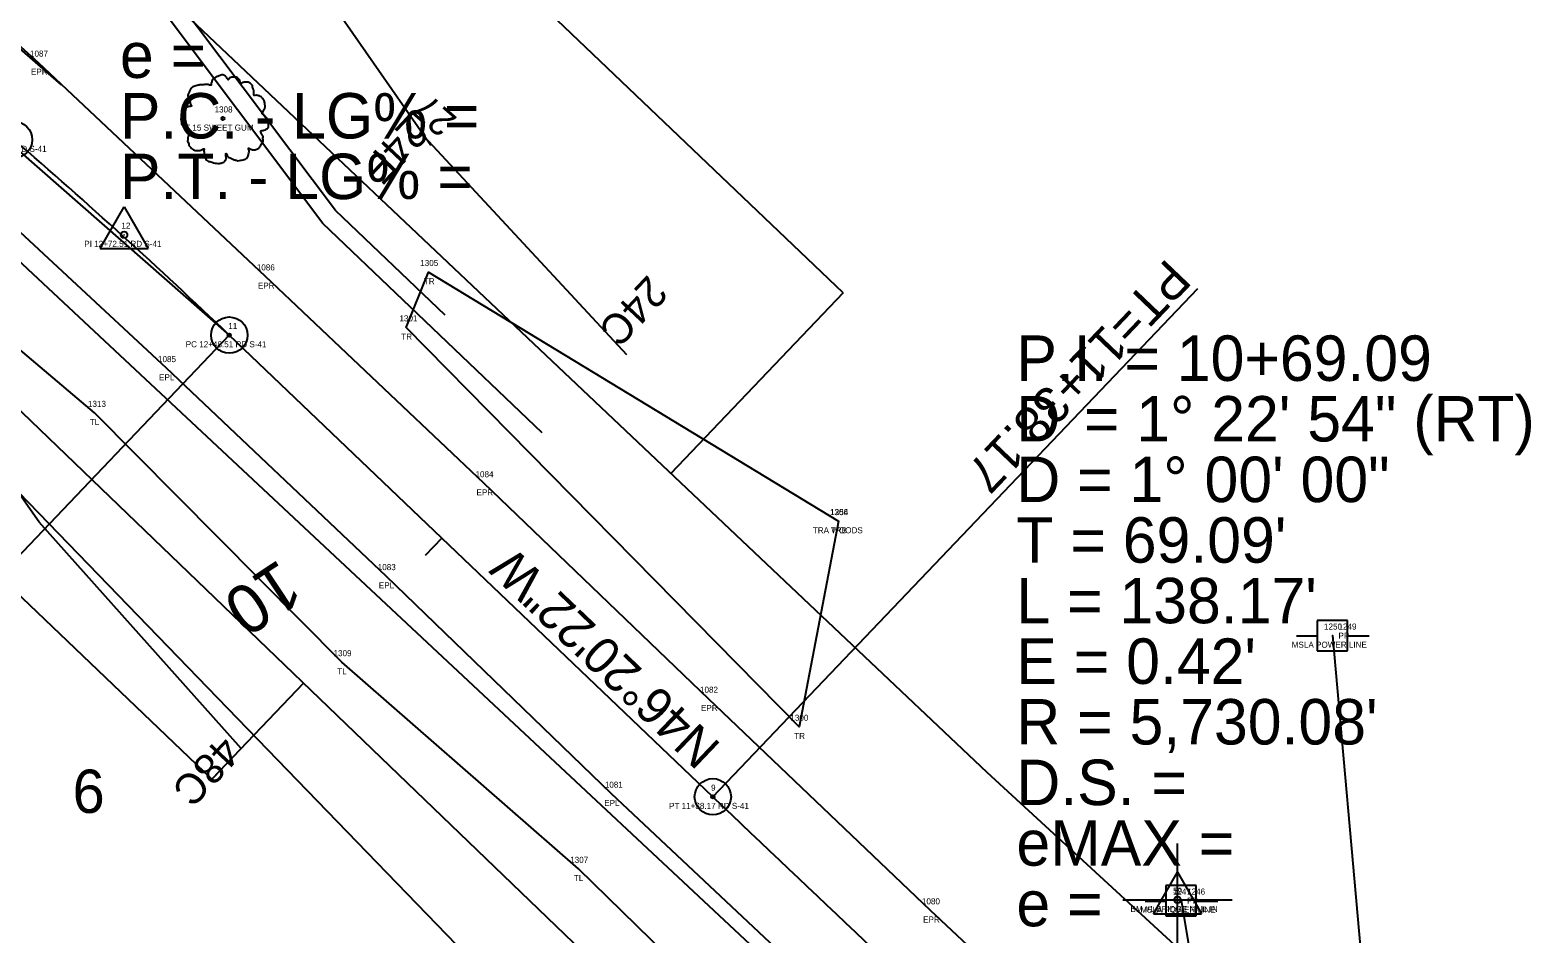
# Model space of a CAD drawing. Extents: x 1812113 to 1819860, y 1177395 to 1181185.
# Drawn here: x 1813853.2 to 1814102.1, y 1178492.8 to 1178641.9 of the extents above; entities that cross this region are included whole.
import ezdxf

# ---------------------------------------------------------------- set-up
doc = ezdxf.new("R2010")
doc.units = 0
for name, color, linetype in [('RD_EX_DV_Prop', 7, 'Continuous'), ('RD_EX_DV_TX_Prop', 7, 'Continuous'), ('RD_EX_Misc', 7, 'Continuous'), ('RD_EX_Misc_txCode', 7, 'Continuous'), ('RD_EX_Road', 7, 'Continuous'), ('RD_EX_Road_txCode', 7, 'Continuous'), ('RD_EX_UT', 7, 'Continuous'), ('RD_EX_UT_txCode', 7, 'Continuous'), ('RD_EX_VEG', 7, 'Continuous'), ('RD_EX_VEG_txCode', 7, 'Continuous'), ('RD_HC_CL', 7, 'Continuous'), ('RD_HC_Data', 7, 'Continuous'), ('RD_HC_Data_Tic', 7, 'Continuous'), ('RD_HC_TX_StaOther', 7, 'Continuous'), ('RD_HC_txCode', 7, 'Continuous'), ('RD_PD_ALT1_TrvlWay', 7, 'Continuous'), ('RD_PD_ALT3_LnLine', 7, 'Continuous'), ('RD_PD_BCA', 7, 'Continuous'), ('RD_PD_PatLn1', 7, 'Continuous'), ('RD_PD_PatLn2', 7, 'Continuous'), ('RD_PD_RW', 7, 'Continuous'), ('RD_SMD_Locator', 7, 'Continuous')]:
    doc.layers.add(name, color=color, linetype=linetype)

msp = doc.modelspace()

# ---------------------------------------------------------------- linework, layer by layer
at = {"layer": 'RD_EX_DV_Prop'}
for p, q in [((1814011.17, 1178519.35), (1813854.67, 1178667.32)), ((1814007.16, 1178429.49), (1813828.61, 1178601.13)), ((1814146.51, 1178395.03), (1814011.17, 1178519.35))]:
    msp.add_line(p, q, dxfattribs=at)
at = {"layer": 'RD_EX_Misc'}
for p, q in [((1814068.17, 1178541.96), (1814086.12, 1178341.27)), ((1814043.18, 1178498.23), (1814070.2, 1178336.93))]:
    msp.add_line(p, q, dxfattribs=at)
at = {"layer": 'RD_EX_Road'}
for p, q in [((1813875.67, 1178586.1), (1813838.32, 1178620.7)), ((1813911.94, 1178551.77), (1813875.67, 1178586.1)), ((1813949.15, 1178515.86), (1813911.94, 1178551.77)), ((1813986.47, 1178480.85), (1813949.15, 1178515.86))]:
    msp.add_line(p, q, dxfattribs=at)
msp.add_lwpolyline([(1814076.45, 1178427.4), (1814038.86, 1178461.87), (1814001.83, 1178496.62), (1813965.15, 1178531.54), (1813928.08, 1178567.1), (1813892.01, 1178601.23), (1813854.54, 1178636.51), (1813817.44, 1178670.03), (1813779.87, 1178701.64)], dxfattribs=at)
at = {"layer": 'RD_EX_UT'}
for p, q in [((1814070.66, 1178544.47), (1814065.66, 1178544.47)), ((1814065.66, 1178544.47), (1814065.66, 1178539.47)), ((1814070.66, 1178539.47), (1814070.66, 1178544.47)), ((1814062.23, 1178541.91), (1814065.7, 1178541.91)), ((1814070.59, 1178541.91), (1814074.23, 1178541.91)), ((1814065.66, 1178539.47), (1814070.66, 1178539.47)), ((1814045.67, 1178500.74), (1814040.67, 1178500.74)), ((1814040.67, 1178500.74), (1814040.67, 1178495.74)), ((1814045.67, 1178495.74), (1814045.67, 1178500.74)), ((1814037.24, 1178498.17), (1814040.71, 1178498.17)), ((1814045.6, 1178498.17), (1814049.24, 1178498.17)), ((1814040.67, 1178495.74), (1814045.67, 1178495.74))]:
    msp.add_line(p, q, dxfattribs=at)
msp.add_lwpolyline([(1814122.48, 1178351.31), (1814099.73, 1178371.68), (1813807.05, 1178645.14), (1813817.45, 1178777.9), (1813883.81, 1178790.87)], dxfattribs=at)
at = {"layer": 'RD_EX_VEG'}
for points in [[(1813964.65, 1178448.48), (1813984.61, 1178463.55), (1813943.71, 1178503.46), (1813904.65, 1178537.57), (1813863.79, 1178578.71), (1813833.99, 1178603.93), (1813823.24, 1178594.53), (1813964.65, 1178448.48)], [(1813986.62, 1178560.85), (1813980.11, 1178526.91), (1813915.24, 1178592.82), (1813918.96, 1178601.96), (1813986.62, 1178560.85)]]:
    msp.add_lwpolyline(points, dxfattribs=at)
for centre, radius in [((1813885.01, 1178627.3), 0.25), ((1813885, 1178627.28), 0.0001)]:
    msp.add_circle(centre, radius, dxfattribs=at)
for points in [[(1813885.14, 1178634.47), (1813884.84, 1178634.49), (1813884.52, 1178634.39), (1813884.27, 1178634.29), (1813884.04, 1178634.22), (1813883.82, 1178634.12), (1813883.52, 1178633.94), (1813883.29, 1178633.74), (1813883.17, 1178633.49), (1813883.12, 1178633.27), (1813883.07, 1178632.99), (1813883.07, 1178632.82), (1813882.94, 1178632.79), (1813882.79, 1178632.82), (1813882.54, 1178632.89), (1813882.29, 1178632.89), (1813882.04, 1178632.89), (1813881.69, 1178632.87), (1813881.34, 1178632.87), (1813881.07, 1178632.82), (1813880.74, 1178632.77), (1813880.37, 1178632.64), (1813880.02, 1178632.52), (1813879.72, 1178632.27), (1813879.47, 1178631.8), (1813879.34, 1178631.45), (1813879.19, 1178631.2), (1813879.34, 1178630.75), (1813879.52, 1178630.4), (1813879.54, 1178630.2), (1813879.62, 1178629.77), (1813879.72, 1178629.55), (1813879.84, 1178629.35), (1813879.77, 1178629.32), (1813879.39, 1178629.27), (1813879.09, 1178629.17), (1813878.67, 1178628.95), (1813878.44, 1178628.72), (1813878.34, 1178628.4), (1813878.32, 1178628.05), (1813878.22, 1178627.85), (1813878.14, 1178627.57), (1813878.12, 1178627.5), (1813878.07, 1178627.17), (1813878.17, 1178626.72), (1813878.19, 1178626.37), (1813878.32, 1178626.15), (1813878.47, 1178625.97), (1813878.64, 1178625.72), (1813879.04, 1178625.5), (1813879.37, 1178625.4), (1813879.57, 1178625.37), (1813879.39, 1178624.87), (1813879.34, 1178624.52), (1813879.22, 1178624.12), (1813879.22, 1178624.05), (1813879.17, 1178623.57), (1813879.32, 1178623.25), (1813879.39, 1178622.87), (1813879.57, 1178622.65), (1813879.84, 1178622.35), (1813880.17, 1178622.12), (1813880.67, 1178622), (1813881.07, 1178622.02), (1813881.64, 1178622.2), (1813881.89, 1178622.27), (1813881.87, 1178622.1), (1813881.89, 1178621.72), (1813881.89, 1178621.3), (1813882.04, 1178620.98), (1813882.14, 1178620.7), (1813882.29, 1178620.45), (1813882.62, 1178620.23), (1813883.02, 1178620.15), (1813883.44, 1178620), (1813883.89, 1178619.93), (1813884.39, 1178619.9), (1813884.99, 1178620.05), (1813885.27, 1178620.18), (1813885.37, 1178620.35), (1813885.57, 1178620.73), (1813885.52, 1178620.95), (1813885.54, 1178621.55), (1813885.64, 1178621.37), (1813885.82, 1178621.02), (1813886.32, 1178620.73), (1813886.72, 1178620.55), (1813887.19, 1178620.4), (1813887.49, 1178620.33), (1813887.96, 1178620.4), (1813888.34, 1178620.48), (1813888.71, 1178620.6), (1813889.01, 1178620.88), (1813889.19, 1178621.15), (1813889.24, 1178621.42), (1813889.31, 1178621.8), (1813889.36, 1178621.97)], [(1813889.36, 1178621.97), (1813889.29, 1178622.15), (1813889.24, 1178622.4), (1813889.31, 1178622.37), (1813889.49, 1178622.32), (1813889.76, 1178622.2), (1813889.99, 1178622.12), (1813890.31, 1178622.15), (1813890.59, 1178622.25), (1813891.04, 1178622.52), (1813891.31, 1178623), (1813891.59, 1178623.4), (1813891.66, 1178623.72), (1813891.61, 1178623.95), (1813891.59, 1178624.45), (1813891.39, 1178624.7), (1813891.34, 1178624.82), (1813891.24, 1178625.22), (1813891.31, 1178625.27), (1813891.59, 1178625.32), (1813891.96, 1178625.45), (1813892.24, 1178625.57), (1813892.46, 1178625.75), (1813892.54, 1178625.97), (1813892.51, 1178626.37), (1813892.56, 1178626.77), (1813892.49, 1178626.92), (1813892.39, 1178627.07), (1813892.31, 1178627.27), (1813892.16, 1178627.42), (1813892.06, 1178627.57), (1813891.96, 1178627.67), (1813891.84, 1178627.82), (1813891.66, 1178627.95), (1813891.51, 1178628), (1813891.46, 1178628.15), (1813891.61, 1178628.35), (1813891.66, 1178628.45), (1813891.69, 1178628.67), (1813891.91, 1178629.02), (1813891.96, 1178629.42), (1813891.91, 1178629.85), (1813891.86, 1178630.12), (1813891.71, 1178630.4), (1813891.51, 1178630.65), (1813891.39, 1178630.82), (1813891.21, 1178630.95), (1813890.89, 1178631.07), (1813890.64, 1178631.12), (1813890.29, 1178631.12), (1813890.09, 1178631.17), (1813890.11, 1178631.22), (1813890.11, 1178631.37), (1813890.11, 1178631.65), (1813890.04, 1178632.1), (1813889.89, 1178632.59), (1813889.89, 1178632.62), (1813889.79, 1178632.87), (1813889.56, 1178633.07), (1813889.39, 1178633.17), (1813889.19, 1178633.29), (1813888.94, 1178633.32), (1813888.64, 1178633.32), (1813888.36, 1178633.27), (1813888.16, 1178633.17), (1813887.99, 1178633.04), (1813887.91, 1178633.19), (1813887.82, 1178633.49), (1813887.77, 1178633.64), (1813887.62, 1178633.82), (1813887.39, 1178634.02), (1813886.94, 1178634.14), (1813886.32, 1178634.07), (1813886.02, 1178633.87), (1813885.87, 1178633.69), (1813885.82, 1178633.82), (1813885.62, 1178634.02), (1813885.52, 1178634.19), (1813885.34, 1178634.32), (1813885.19, 1178634.42), (1813885.09, 1178634.47)]]:
    msp.add_spline(points, degree=3, dxfattribs=at)
at = {"layer": 'RD_HC_CL'}
msp.add_line((1813965.88, 1178515.37), (1813886.05, 1178591.55), dxfattribs=at)
for centre, radius, start, end in [((1813226.77, 1177900.71), 954.94, 46.33932, 49.21843), ((1817921.84, 1182660.75), 5730.08, 226.33932, 227.720866)]:
    msp.add_arc(centre, radius, start, end, dxfattribs=at)
at = {"layer": 'RD_HC_Data'}
for p, q in [((1813864.72, 1178605.83), (1813868.69, 1178612.71)), ((1813868.69, 1178612.71), (1813872.66, 1178605.83)), ((1813864.72, 1178605.83), (1813872.66, 1178605.83)), ((1813965.88, 1178515.37), (1814045.93, 1178599.26)), ((1813886.05, 1178591.55), (1813805.93, 1178507.6)), ((1814042.6, 1178489.32), (1814042.6, 1178507.65)), ((1814038.63, 1178496.06), (1814042.6, 1178502.94)), ((1814042.6, 1178502.94), (1814046.57, 1178496.06)), ((1814033.56, 1178498.36), (1814051.64, 1178498.36)), ((1814038.63, 1178496.06), (1814046.57, 1178496.06))]:
    msp.add_line(p, q, dxfattribs=at)
for centre, radius in [((1813850.52, 1178623.8), 3), ((1813868.69, 1178608.12), 0.529), ((1813886.05, 1178591.55), 3), ((1813886.05, 1178591.55), 0.282), ((1813965.88, 1178515.37), 3), ((1813965.88, 1178515.37), 0.282), ((1814042.6, 1178498.36), 0.529)]:
    msp.add_circle(centre, radius, dxfattribs=at)
at = {"layer": 'RD_HC_Data_Tic'}
msp.add_line((1813921.14, 1178558.06), (1813918.38, 1178555.17), dxfattribs=at)
at = {"layer": 'RD_PD_ALT1_TrvlWay'}
msp.add_line((1813858.35, 1178632.88), (1813779.98, 1178700.49), dxfattribs=at)
at = {"layer": 'RD_PD_ALT3_LnLine'}
for p, q in [((1813903.58, 1178612.14), (1813872.03, 1178654.1)), ((1813901.51, 1178609.97), (1813870.07, 1178651.83)), ((1813921.7, 1178594.86), (1813903.58, 1178612.14)), ((1813937.71, 1178575.43), (1813901.51, 1178609.97)), ((1813854.64, 1178560.7), (1813826.31, 1178601.1)), ((1813888, 1178523.34), (1813854.64, 1178560.7))]:
    msp.add_line(p, q, dxfattribs=at)
at = {"layer": 'RD_PD_BCA'}
for p, q in [((1813919.31, 1178622.84), (1813889.1, 1178666.28)), ((1813951.67, 1178588.32), (1813917.54, 1178625.04))]:
    msp.add_line(p, q, dxfattribs=at)
at = {"layer": 'RD_PD_PatLn1'}
msp.add_line((1813775.64, 1178688.14), (1813886.05, 1178591.55), dxfattribs=at)
at = {"layer": 'RD_PD_PatLn2'}
msp.add_line((1813884.87, 1178520.06), (1813883.18, 1178518.26), dxfattribs=at)
at = {"layer": 'RD_PD_RW'}
for p, q in [((1813987.39, 1178598.51), (1813937.83, 1178645.81)), ((1813987.39, 1178598.51), (1813958.96, 1178568.72)), ((1813883.18, 1178518.26), (1813848.08, 1178551.76)), ((1813898.3, 1178534.13), (1813883.17, 1178518.27))]:
    msp.add_line(p, q, dxfattribs=at)
at = {"layer": 'RD_SMD_Locator'}
for centre in [(1813854.54, 1178636.51), (1813868.69, 1178608.12), (1813918.96, 1178601.96), (1813892.01, 1178601.23), (1813915.24, 1178592.82), (1813886.05, 1178591.55), (1813875.67, 1178586.1), (1813863.79, 1178578.71), (1813928.08, 1178567.1), (1813986.62, 1178560.85), (1813986.62, 1178560.85), (1813911.94, 1178551.77), (1814068.17, 1178541.96), (1813904.65, 1178537.57), (1813965.15, 1178531.54), (1813980.11, 1178526.91), (1813949.15, 1178515.86), (1813965.88, 1178515.37), (1813943.71, 1178503.46), (1814042.6, 1178498.36), (1814043.18, 1178498.23), (1814001.83, 1178496.62)]:
    msp.add_circle(centre, 0.001, dxfattribs=at)

# ---------------------------------------------------------------- texts
at = {"layer": 'RD_EX_DV_TX_Prop'}
msp.add_text('6', height=7.14, dxfattribs=at).set_placement((1813860.18, 1178512.71))
at = {"layer": 'RD_EX_Misc_txCode'}
for s, p in [('1250', (1814066.78, 1178542.96)), ('MSLA POWER LINE', (1814061.45, 1178539.96)), ('1247', (1814041.83, 1178499.23)), ('MSLA POWER LINE', (1814036.47, 1178496.23))]:
    msp.add_text(s, height=1, dxfattribs=at).set_placement(p)
at = {"layer": 'RD_EX_Road_txCode'}
for s, p in [('1087', (1813853.15, 1178637.51)), ('EPR', (1813853.31, 1178634.51)), ('1086', (1813890.6, 1178602.23)), ('EPR', (1813890.78, 1178599.23)), ('1085', (1813874.28, 1178587.1)), ('EPL', (1813874.46, 1178584.1)), ('1084', (1813926.7, 1178568.1)), ('EPR', (1813926.86, 1178565.1)), ('1083', (1813910.56, 1178552.77)), ('EPL', (1813910.74, 1178549.77)), ('1082', (1813963.76, 1178532.54)), ('EPR', (1813963.92, 1178529.54)), ('1081', (1813948.05, 1178516.86)), ('EPL', (1813947.95, 1178513.86)), ('1080', (1814000.4, 1178497.62)), ('EPR', (1814000.6, 1178494.62))]:
    msp.add_text(s, height=1, dxfattribs=at).set_placement(p)
at = {"layer": 'RD_EX_UT_txCode'}
for s, p in [('1249', (1814069.17, 1178542.96)), ('PP', (1814069.17, 1178541.46)), ('1246', (1814044.18, 1178499.23)), ('PP', (1814044.18, 1178497.73))]:
    msp.add_text(s, height=1, dxfattribs=at).set_placement(p)
at = {"layer": 'RD_EX_VEG_txCode'}
for s, p in [('1308', (1813883.62, 1178628.3)), ('T 15 SWEET GUM', (1813878.77, 1178625.3)), ('1305', (1813917.57, 1178602.96)), ('TR', (1813918.17, 1178599.96)), ('1301', (1813914.14, 1178593.82)), ('TR', (1813914.44, 1178590.82)), ('1313', (1813862.72, 1178579.71)), ('TL', (1813863.02, 1178576.71)), ('1306', (1813985.21, 1178561.85)), ('1254', (1813985.27, 1178561.85)), ('TRA WOODS', (1813982.39, 1178558.85)), ('TRB', (1813985.35, 1178558.85)), ('1309', (1813903.26, 1178538.57)), ('TL', (1813903.88, 1178535.57)), ('1300', (1813978.68, 1178527.91)), ('TR', (1813979.31, 1178524.91)), ('1307', (1813942.33, 1178504.46)), ('TL', (1813942.94, 1178501.46))]:
    msp.add_text(s, height=1, dxfattribs=at).set_placement(p)
at = {"layer": 'RD_HC_Data'}
for s, rotation, p in [('PT=11+38.17', 226.3393, (1814040.87, 1178604.39)), ('N46%%d20\'22"W', 136.3393, (1813967.43, 1178523.88))]:
    msp.add_text(s, height=6, rotation=rotation, dxfattribs=at).set_placement(p)
at = {"layer": 'RD_HC_TX_StaOther'}
for s, p in [('e = ', (1813868, 1178634)), ('P.C. - LG% = ', (1813868, 1178624)), ('P.T. - LG% = ', (1813868, 1178614)), ('P.I. = 10+69.09', (1814016, 1178584)), ('D', (1814016, 1178574)), ('    = 1%%d 22\' 54" (RT)', (1814016, 1178574)), ('D = 1%%d 00\' 00"', (1814016, 1178564)), ("T = 69.09'", (1814016, 1178554)), ("L = 138.17'", (1814016, 1178544)), ("E = 0.42'", (1814016, 1178534)), ("R = 5,730.08'", (1814016, 1178524)), ('D.S. = ', (1814016, 1178514)), ('eMAX = ', (1814016, 1178504)), ('e = ', (1814016, 1178494))]:
    msp.add_text(s, height=7.5, dxfattribs=at).set_placement(p)
msp.add_text('10', height=8, rotation=213.5168, dxfattribs=at).set_placement((1813894.38, 1178554.73))
at = {"layer": 'RD_HC_txCode'}
for s, p in [('PT 12+96.49 RD S-41', (1813842.7, 1178621.8)), ('12', (1813868.24, 1178609.12)), ('PI 12+72.51 RD S-41', (1813862.11, 1178606.12)), ('11', (1813885.88, 1178592.55)), ('PC 12+48.51 RD S-41', (1813878.86, 1178589.55)), ('9', (1813965.59, 1178516.37)), ('PT 11+38.17 RD S-41', (1813958.65, 1178513.37)), ('59', (1814041.87, 1178499.36)), ('BM #1 BRIDGE NAIL IN', (1814034.83, 1178496.36))]:
    msp.add_text(s, height=1, dxfattribs=at).set_placement(p)
at = {"layer": 'RD_PD_ALT3_LnLine'}
for s, height, rotation, p in [('27', 4.5, 138.8497, (1813923.85, 1178627.33)), ('24F', 5, 226.7234, (1813915.66, 1178627.98)), ('24C', 5, 226.7234, (1813955.18, 1178601.67)), ('48C', 5, 226.7234, (1813884.74, 1178525.76))]:
    msp.add_text(s, height=height, rotation=rotation, dxfattribs=at).set_placement(p)

doc.saveas('drawing.dxf')
